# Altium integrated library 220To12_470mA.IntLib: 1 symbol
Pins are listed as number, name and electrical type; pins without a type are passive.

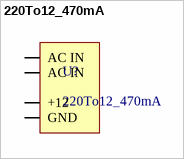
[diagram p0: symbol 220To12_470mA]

## 220To12_470mA
designator U?
footprint 220To12_470mA
pins: 1 AC IN, 2 AC IN, 3 +12, 4 GND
